(* Logix 5000 project; controller SD_Card_Example vendor 1 type 14 code 193 rev 33.12; software revision 33.01 *)

TASK MainTask (periodic, rate 1 ms, priority 10, watchdog 500 ms) : MainProgram

MODULES
   Local : vendor 1 type 14 code 193 (5069 0, rev 33.12)
END_MODULES

TYPE SD_Arrays :   // Contains the arrays that store the sent and received CIP data for the SD card library
STRUCT
   source : SINT[4000];
   destination : SINT[4000];
END_STRUCT
END_TYPE

ADD_ON_INSTRUCTION SD_CloseFile   (* revision 1.0 *)
// Closes an open file on the SD card
VAR_INPUT
   Execute : BOOL; {required}   // Execution of the function block begins on a rising edge of this input
   FileHandle : DINT; {required}   // Handle of file to close
END_VAR
VAR_OUTPUT
   Done : BOOL; {visible}   // Command has finished successfully, any returned values can be used
   Error : BOOL; {visible}   // Error occured during execution
   ErrorCode : INT; {visible}   // CIP message error code
   ErrorCodeExtended : DINT; {visible}   // CIP message error code extended
END_VAR
VAR_IN_OUT
   Message_54 : MESSAGE; {required}   // Message to send to SD card reader, MUST HAVE SERVICE CODE 54!!!
   Arrays : SD_Arrays; {required}
END_VAR

ROUTINE Logic   (* ladder *)
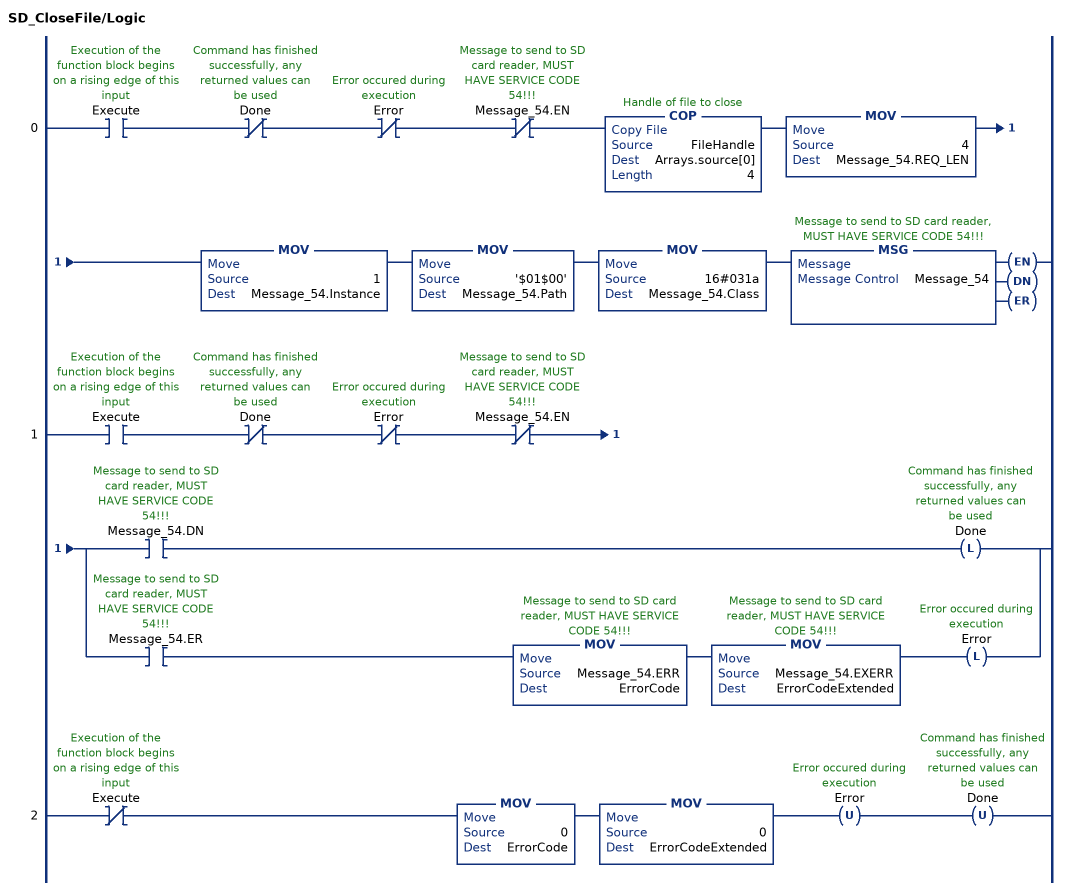
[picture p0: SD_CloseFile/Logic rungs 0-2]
   0: XIC(Execute)XIO(Done)XIO(Error)XIO(Message_54.EN)COP(FileHandle,Arrays.source[0],4)MOV(4,Message_54.REQ_LEN)MOV(1,Message_54.Instance)MOV('$01$00',Message_54.Path)MOV(16#031a,Message_54.Class)MSG(Message_54);
   1: XIC(Execute)XIO(Done)XIO(Error)XIO(Message_54.EN)[XIC(Message_54.DN) OTL(Done) ,XIC(Message_54.ER) MOV(Message_54.ERR,ErrorCode) MOV(Message_54.EXERR,ErrorCodeExtended) OTL(Error) ];
   2: XIO(Execute)MOV(0,ErrorCode)MOV(0,ErrorCodeExtended)OTU(Error)OTU(Done);
END_ROUTINE
END_ADD_ON_INSTRUCTION

ADD_ON_INSTRUCTION SD_CreateFile   (* revision 1.0 *)
// Creates and opens file on the SD card (will return an error if the file already exist on the card)
VAR_INPUT
   Execute : BOOL; {required}   // Execution of the function block begins on a rising edge of this input
END_VAR
VAR_IN_OUT
   FileName : STRING; {required}   // Name of the file
END_VAR
VAR_OUTPUT
   Done : BOOL; {visible}   // Command has finished successfully, any returned values can be used
   Error : BOOL; {visible}   // Error occured during execution
   ErrorCode : INT; {visible}   // CIP message error code
   ErrorCodeExtended : DINT; {visible}   // CIP message error code extended
   FileHandle : DINT; {visible}   // Returned file handle
END_VAR
VAR_IN_OUT
   Message_52 : MESSAGE; {required}   // Message to send to SD card reader, MUST HAVE SERVICE CODE 52!!!
   Arrays : SD_Arrays; {required}
END_VAR
VAR
   OpenCreateParameters : SINT[24] := ([3] := -64, [12] := 1, [16] := -128); {access None}
   MessageReady : BOOL; {access None}
   RequestCleared : BOOL; {access None}
   LoopCount : DINT; {access None}
END_VAR

ROUTINE Logic   (* ladder *)
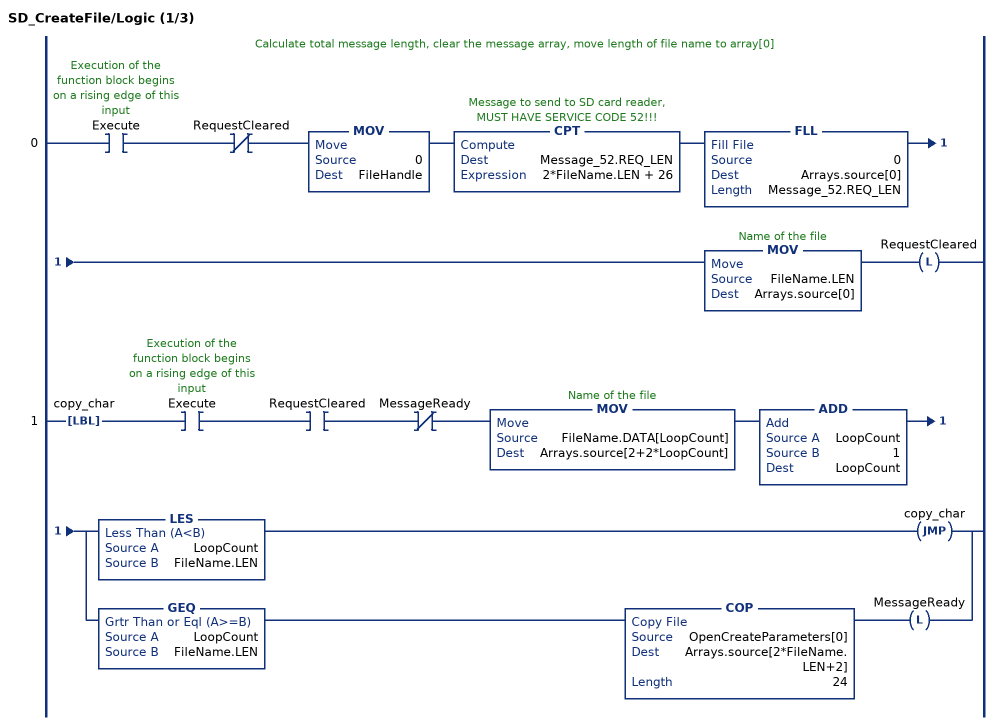
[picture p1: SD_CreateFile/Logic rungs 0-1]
   // Calculate total message length, clear the message array, move length of file name to array[0]
   0: XIC(Execute)XIO(RequestCleared)MOV(0,FileHandle)CPT(Message_52.REQ_LEN,2*FileName.LEN + 26)FLL(0,Arrays.source[0],Message_52.REQ_LEN)MOV(FileName.LEN,Arrays.source[0])OTL(RequestCleared);
   1: LBL(copy_char)XIC(Execute)XIC(RequestCleared)XIO(MessageReady)MOV(FileName.DATA[LoopCount],Arrays.source[2+2*LoopCount])ADD(LoopCount,1,LoopCount)[LES(LoopCount,FileName.LEN) JMP(copy_char) ,GEQ(LoopCount,FileName.LEN) COP(OpenCreateParameters[0],Arrays.source[2*FileName.LEN+2],24) OTL(MessageReady) ];
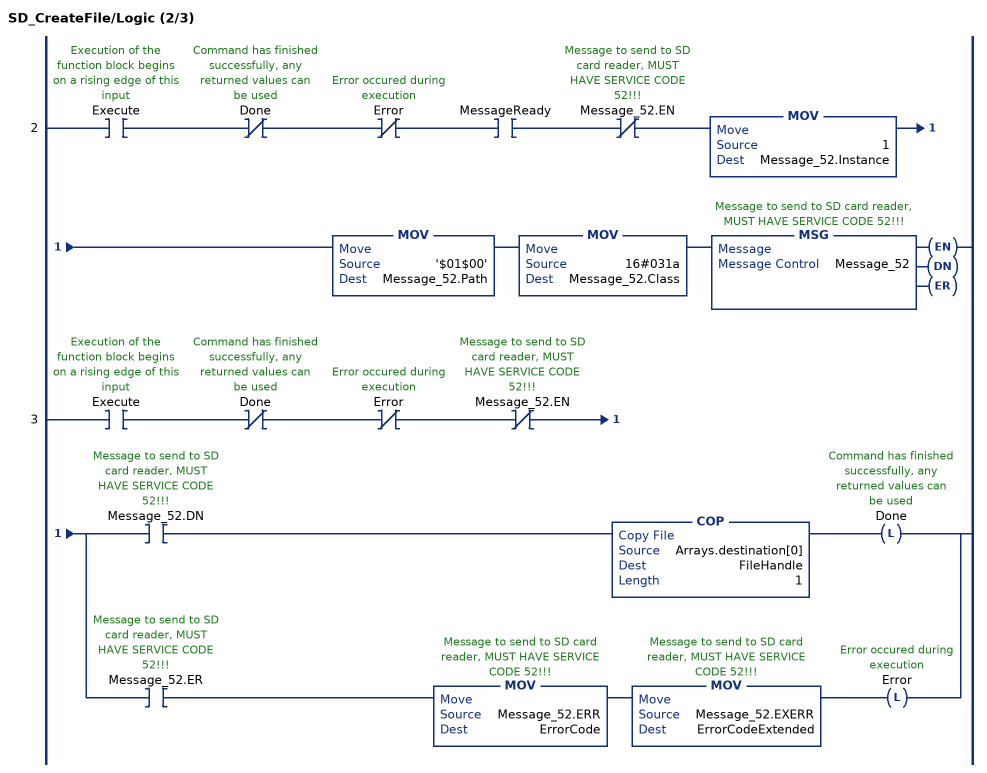
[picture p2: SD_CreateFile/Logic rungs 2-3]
   2: XIC(Execute)XIO(Done)XIO(Error)XIC(MessageReady)XIO(Message_52.EN)MOV(1,Message_52.Instance)MOV('$01$00',Message_52.Path)MOV(16#031a,Message_52.Class)MSG(Message_52);
   3: XIC(Execute)XIO(Done)XIO(Error)XIO(Message_52.EN)[XIC(Message_52.DN) COP(Arrays.destination[0],FileHandle,1) OTL(Done) ,XIC(Message_52.ER) MOV(Message_52.ERR,ErrorCode) MOV(Message_52.EXERR,ErrorCodeExtended) OTL(Error) ];
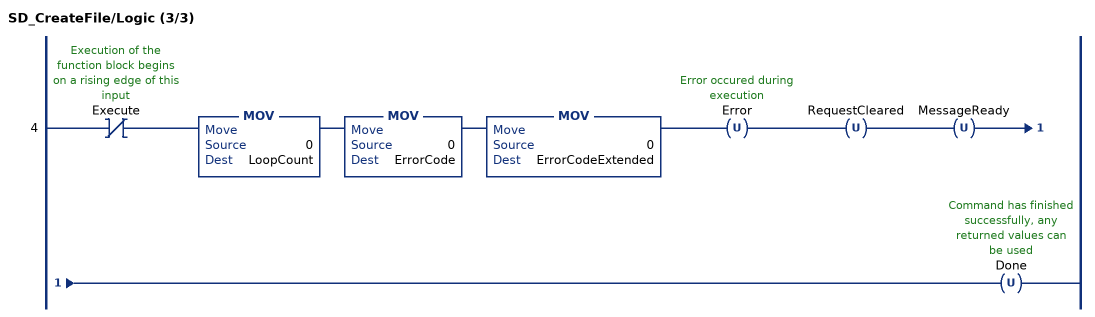
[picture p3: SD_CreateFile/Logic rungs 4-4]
   4: XIO(Execute)MOV(0,LoopCount)MOV(0,ErrorCode)MOV(0,ErrorCodeExtended)OTU(Error)OTU(RequestCleared)OTU(MessageReady)OTU(Done);
END_ROUTINE
END_ADD_ON_INSTRUCTION

ADD_ON_INSTRUCTION SD_DeleteFile   (* revision 1.0 *)
// Deletes a file on the SD card
VAR_INPUT
   Execute : BOOL; {required}   // Execution of the function block begins on a rising edge of this input
END_VAR
VAR_IN_OUT
   FileName : STRING; {required}   // Name of the file
END_VAR
VAR_OUTPUT
   Done : BOOL; {visible}   // Command has finished successfully, any returned values can be used
   Error : BOOL; {visible}   // Error occured during execution
   ErrorCode : INT; {visible}   // CIP message error code
   ErrorCodeExtended : DINT; {visible}   // CIP message error code extended
END_VAR
VAR_IN_OUT
   Message_55 : MESSAGE; {required}   // Message to send to SD card reader, MUST HAVE SERVICE CODE 55!!!
   Arrays : SD_Arrays; {required}
END_VAR
VAR
   MessageReady : BOOL; {access None}
   RequestCleared : BOOL; {access None}
   LoopCount : DINT; {access None}
END_VAR

ROUTINE Logic   (* ladder *)
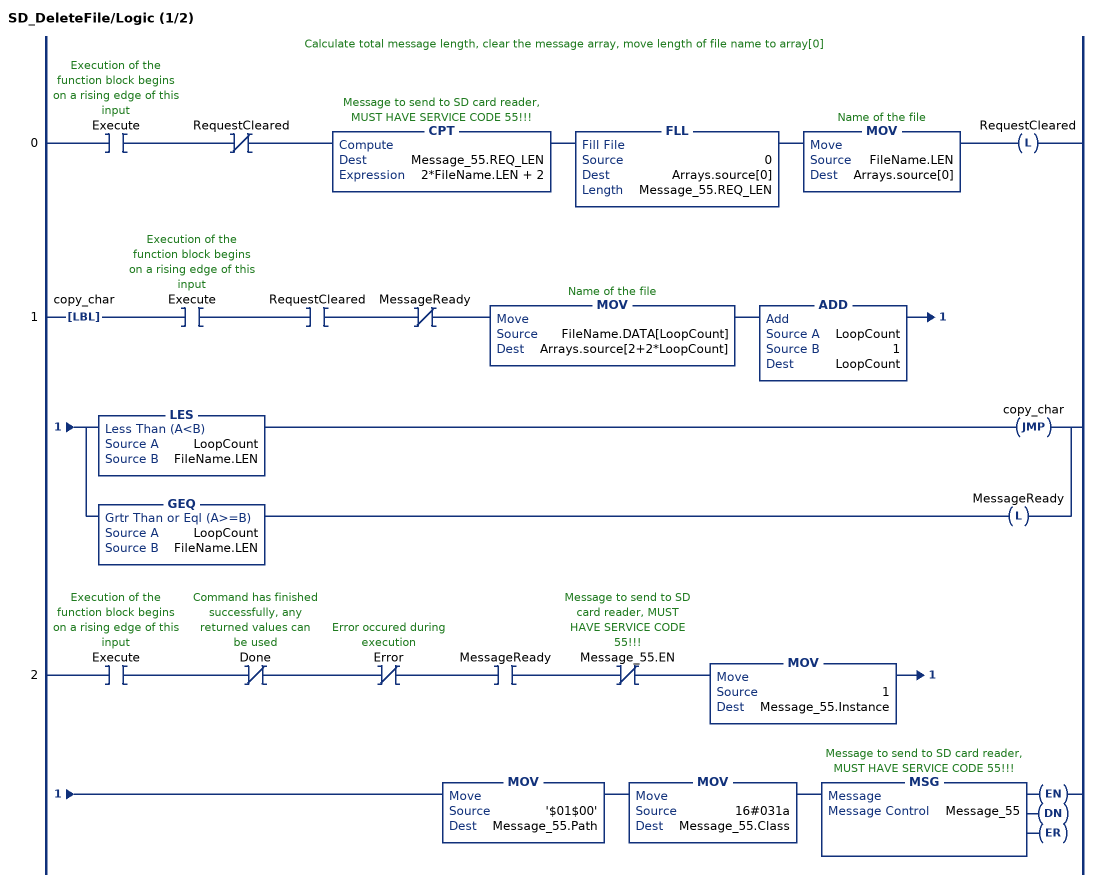
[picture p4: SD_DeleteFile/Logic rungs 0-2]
   // Calculate total message length, clear the message array, move length of file name to array[0]
   0: XIC(Execute)XIO(RequestCleared)CPT(Message_55.REQ_LEN,2*FileName.LEN + 2)FLL(0,Arrays.source[0],Message_55.REQ_LEN)MOV(FileName.LEN,Arrays.source[0])OTL(RequestCleared);
   1: LBL(copy_char)XIC(Execute)XIC(RequestCleared)XIO(MessageReady)MOV(FileName.DATA[LoopCount],Arrays.source[2+2*LoopCount])ADD(LoopCount,1,LoopCount)[LES(LoopCount,FileName.LEN) JMP(copy_char) ,GEQ(LoopCount,FileName.LEN) OTL(MessageReady) ];
   2: XIC(Execute)XIO(Done)XIO(Error)XIC(MessageReady)XIO(Message_55.EN)MOV(1,Message_55.Instance)MOV('$01$00',Message_55.Path)MOV(16#031a,Message_55.Class)MSG(Message_55);
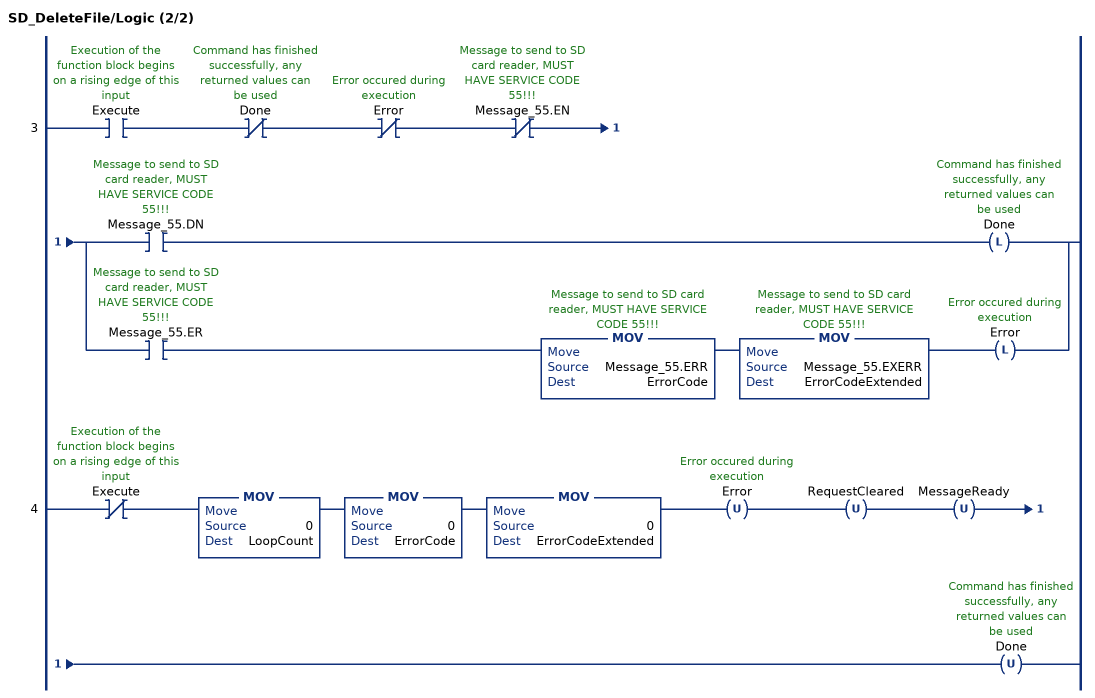
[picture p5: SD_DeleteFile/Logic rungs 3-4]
   3: XIC(Execute)XIO(Done)XIO(Error)XIO(Message_55.EN)[XIC(Message_55.DN) OTL(Done) ,XIC(Message_55.ER) MOV(Message_55.ERR,ErrorCode) MOV(Message_55.EXERR,ErrorCodeExtended) OTL(Error) ];
   4: XIO(Execute)MOV(0,LoopCount)MOV(0,ErrorCode)MOV(0,ErrorCodeExtended)OTU(Error)OTU(RequestCleared)OTU(MessageReady)OTU(Done);
END_ROUTINE
END_ADD_ON_INSTRUCTION

ADD_ON_INSTRUCTION SD_DetectCard   (* revision 1.0 *)
// Detects whether the SD card is present
VAR_INPUT
   Execute : BOOL; {required}   // Execution of the function block begins on a rising edge of this input
END_VAR
VAR_OUTPUT
   Done : BOOL; {visible}   // Command has finished successfully, any returned values can be used
   Error : BOOL; {visible}   // Error occured during execution
   ErrorCode : INT; {visible}   // CIP message error code
   ErrorCodeExtended : DINT; {visible}   // CIP message error code extended
   CardPresent : BOOL; {visible}   // SD card detected
END_VAR
VAR_IN_OUT
   Message_03 : MESSAGE; {required}   // Message to send to SD card reader, MUST HAVE SERVICE CODE 03!!!
   Arrays : SD_Arrays; {required}
END_VAR
VAR
   Get_Status : SINT[4] := ([0] := 1, [2] := 3); {access None}
END_VAR

ROUTINE Logic   (* ladder *)
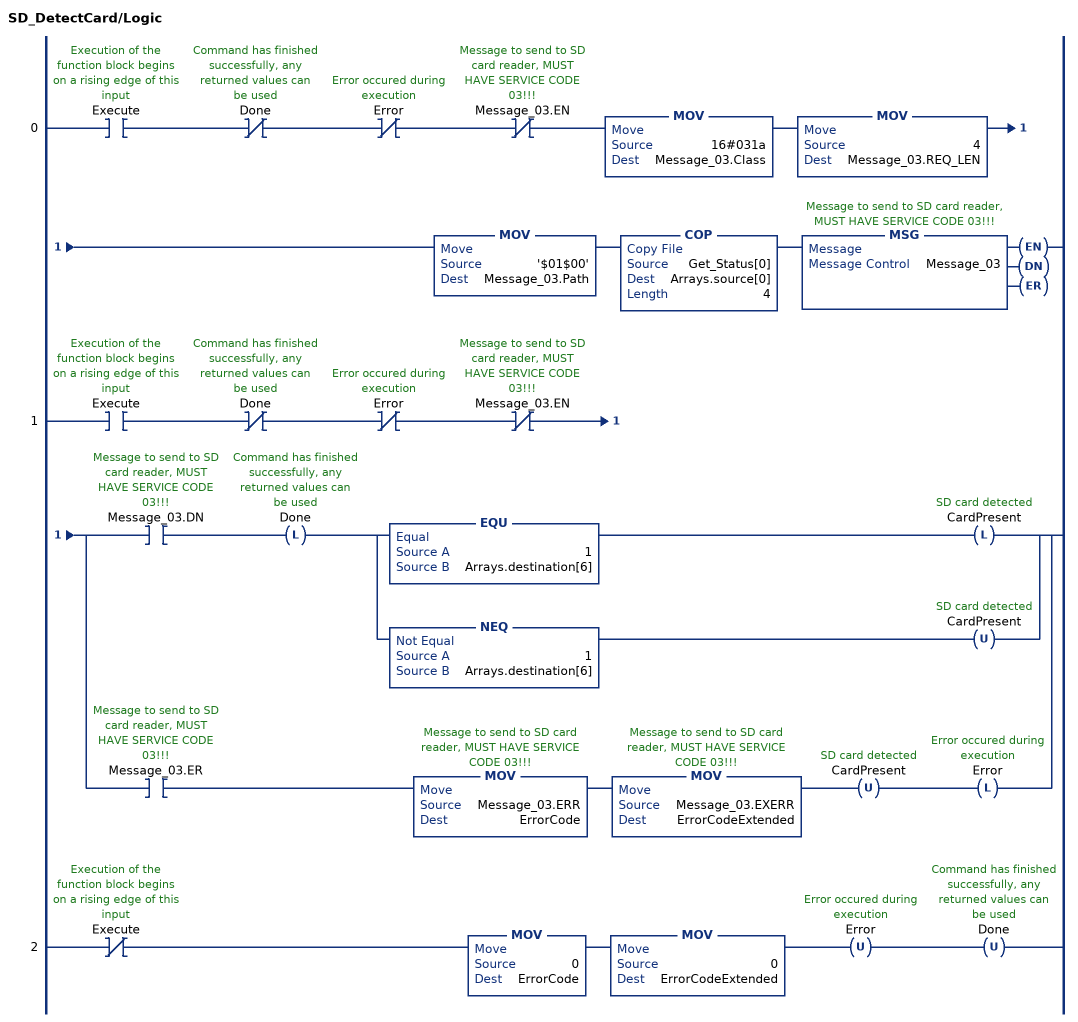
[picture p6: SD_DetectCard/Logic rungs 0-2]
   0: XIC(Execute)XIO(Done)XIO(Error)XIO(Message_03.EN)MOV(16#031a,Message_03.Class)MOV(4,Message_03.REQ_LEN)MOV('$01$00',Message_03.Path)COP(Get_Status[0],Arrays.source[0],4)MSG(Message_03);
   1: XIC(Execute)XIO(Done)XIO(Error)XIO(Message_03.EN)[XIC(Message_03.DN) OTL(Done) [EQU(1,Arrays.destination[6]) OTL(CardPresent) ,NEQ(1,Arrays.destination[6]) OTU(CardPresent) ] ,XIC(Message_03.ER) MOV(Message_03.ERR,ErrorCode) MOV(Message_03.EXERR,ErrorCodeExtended) OTU(CardPresent) OTL(Error) ];
   2: XIO(Execute)MOV(0,ErrorCode)MOV(0,ErrorCodeExtended)OTU(Error)OTU(Done);
END_ROUTINE
END_ADD_ON_INSTRUCTION

ADD_ON_INSTRUCTION SD_Logging   (* revision 1.0 *)
// Create a text file for data logging. Buffer string writes to the log file and dump them to the file when the buffer is greater than a threshold. NOTE: when logging is the current contents of the buffer won't be written.
VAR_INPUT
   Execute : BOOL; {required}   // Create the logging file and start recording data
END_VAR
VAR_IN_OUT
   FileName : STRING; {required}   // Name of the log file to create
END_VAR
VAR_INPUT
   BufferSize : DINT := 1000; {required}   // Number of bytes to buffer before dumping to file (must be < 65535)
END_VAR
VAR_IN_OUT
   NewString : STRING; {required}   // New data to add to the log file. If you don't wish to add new data this cycle give an empty string
END_VAR
VAR_INPUT
   StopLogging : BOOL; {required}   // Stop the logging process and close the file.
END_VAR
VAR_OUTPUT
   LoggingReady : BOOL; {visible}   // Log file has been created and logging has begun
   LoggingFinished : BOOL; {visible}   // File has been closed and the SD card can be safely removed
   Error : BOOL; {visible}   // Error occured during execution
   ErrorCode : INT; {visible}   // CIP message error code
   ErrorCodeExtended : DINT; {visible}   // CIP message error code extended
END_VAR
VAR_IN_OUT
   WriteFileArray : SINT[500000]; {required}   // Array for writing to the file
   Message_52 : MESSAGE; {required}   // Message to send to SD card reader, MUST HAVE SERVICE CODE 52!!!
   Message_50 : MESSAGE; {required}   // Message to send to SD card reader, MUST HAVE SERVICE CODE 50!!!
   Message_54 : MESSAGE; {required}   // Message to send to SD card reader, MUST HAVE SERVICE CODE 54!!!
   Arrays : SD_Arrays; {required}
END_VAR
VAR
   CloseFile : SD_CloseFile; {access None}
   WriteFile : SD_WriteFile; {access None}
   CreateFile : SD_CreateFile; {access None}
   CloseFileExecute : BOOL; {access None}
   CurrentlyWriting : BOOL; {access None}
   BufferDataSize : DINT; {access None}
   DataBeingWrittenSize : DINT; {access None}
   BufferData : SINT[65535]; {access None}
END_VAR

ROUTINE Logic   (* structured text *)
// Create a text file for data logging. Buffer string writes to the log file and dump them to the file when the buffer is greater than a threshold.
   //reset logging
   if(not(Execute))then
   	CurrentlyWriting := 0;
   	DataBeingWrittenSize := 0;
   	BufferDataSize := 0;
   	StopLogging := 0;
   	LoggingReady := 0;
   	LoggingFinished := 0;
   	Error := 0;
   	ErrorCode := 0;
   	ErrorCodeExtended := 0;
   end_if;
   
   //Create the log file
   SD_CreateFile(CreateFile,Execute,FileName,Message_52,Arrays);
   LoggingReady := CreateFile.Done;
   
   //Record the data
   if(CreateFile.Done)then
   	//write new data to log buffer
   	if(not(StopLogging))then
   		COP(NewString.DATA[0],BufferData[BufferDataSize],NewString.LEN);
   		BufferDataSize := BufferDataSize + NewString.LEN;
   		//if enough data recorded, dump to file
   		if(BufferDataSize >= BufferSize)then
   			CurrentlyWriting := 1;
   		end_if;
   	end_if;
   
   	//copy log buffer to writing buffer. Then reset log buffer
   	if(CurrentlyWriting and DataBeingWrittenSize = 0)then
   		COP(BufferData[0],WriteFileArray[0],BufferDataSize);
   		DataBeingWrittenSize := BufferDataSize;
   		BufferDataSize := 0;
   	end_if;
   end_if;
   
   //write the writing buffer to the file
   SD_WriteFile(WriteFile,CurrentlyWriting,CreateFile.FileHandle,DataBeingWrittenSize,WriteFileArray,Message_50,Arrays);
   if(WriteFile.Done)then
   	CurrentlyWriting := 0;
   	DataBeingWrittenSize := 0;
   end_if;
   
   //close the file
   CloseFileExecute := StopLogging and not(CurrentlyWriting);
   SD_CloseFile(CloseFile,CloseFileExecute,CreateFile.FileHandle,Message_54,Arrays);
   LoggingFinished := CloseFile.Done;
   
   //Error handling
   if(CreateFile.Error)then
   	Error := CreateFile.Error;
   	ErrorCode := CreateFile.ErrorCode;
   	ErrorCodeExtended := CreateFile.ErrorCodeExtended;
   end_if;
   if(WriteFile.Error)then
   	Error := WriteFile.Error;
   	ErrorCode := WriteFile.ErrorCode;
   	ErrorCodeExtended := WriteFile.ErrorCodeExtended;
   end_if;
   if(CloseFile.Error)then
   	Error := CloseFile.Error;
   	ErrorCode := CloseFile.ErrorCode;
   	ErrorCodeExtended := CloseFile.ErrorCodeExtended;
   end_if;
   if(Error)then //reset buffer if error occurs to prevent buffer overflow
   	CurrentlyWriting := 0;
   	DataBeingWrittenSize := 0;
   	BufferDataSize := 0;
   end_if;
END_ROUTINE
END_ADD_ON_INSTRUCTION

ADD_ON_INSTRUCTION SD_OpenFile   (* revision 1.0 *)
// Opens a file on the SD card (will return error if file doesn't exist on the SD card)
VAR_INPUT
   Execute : BOOL; {required}   // Execution of the function block begins on a rising edge of this input
END_VAR
VAR_IN_OUT
   FileName : STRING; {required}   // Name of the file
END_VAR
VAR_OUTPUT
   Done : BOOL; {visible}   // Command has finished successfully, any returned values can be used
   Error : BOOL; {visible}   // Error occured during execution
   ErrorCode : INT; {visible}   // CIP message error code
   ErrorCodeExtended : DINT; {visible}   // CIP message error code extended
   FileHandle : DINT; {visible}   // Returned file handle
END_VAR
VAR_IN_OUT
   Message_52 : MESSAGE; {required}   // Message to send to SD card reader, MUST HAVE SERVICE CODE 52!!!
   Arrays : SD_Arrays; {required}
END_VAR
VAR
   OpenCreateParameters : SINT[24] := ([3] := -64, [12] := 3, [16] := -128); {access None}
   MessageReady : BOOL; {access None}
   RequestCleared : BOOL; {access None}
   LoopCount : DINT; {access None}
END_VAR

ROUTINE Logic   (* ladder *)
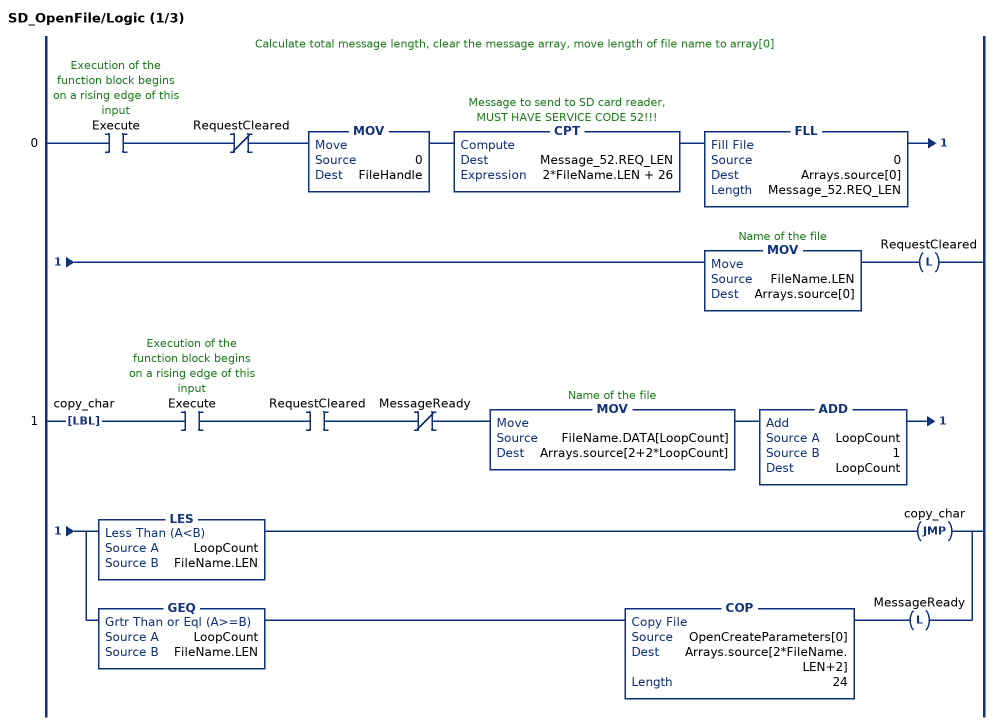
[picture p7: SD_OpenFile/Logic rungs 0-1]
   // Calculate total message length, clear the message array, move length of file name to array[0]
   0: XIC(Execute)XIO(RequestCleared)MOV(0,FileHandle)CPT(Message_52.REQ_LEN,2*FileName.LEN + 26)FLL(0,Arrays.source[0],Message_52.REQ_LEN)MOV(FileName.LEN,Arrays.source[0])OTL(RequestCleared);
   1: LBL(copy_char)XIC(Execute)XIC(RequestCleared)XIO(MessageReady)MOV(FileName.DATA[LoopCount],Arrays.source[2+2*LoopCount])ADD(LoopCount,1,LoopCount)[LES(LoopCount,FileName.LEN) JMP(copy_char) ,GEQ(LoopCount,FileName.LEN) COP(OpenCreateParameters[0],Arrays.source[2*FileName.LEN+2],24) OTL(MessageReady) ];
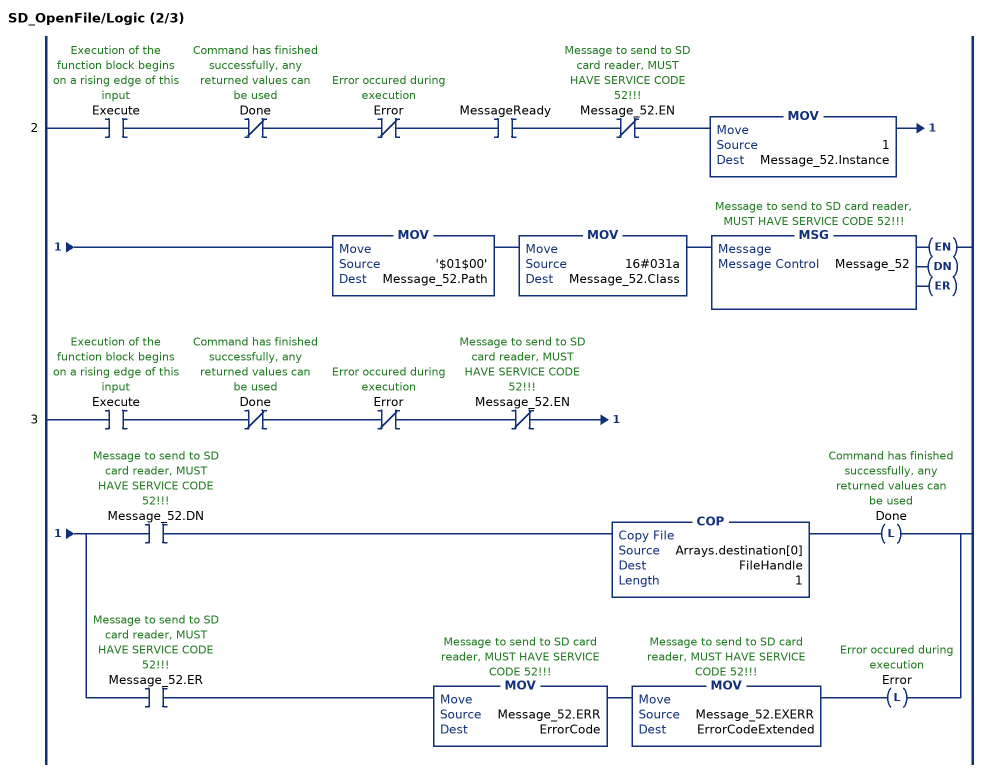
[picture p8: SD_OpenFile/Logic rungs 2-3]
   2: XIC(Execute)XIO(Done)XIO(Error)XIC(MessageReady)XIO(Message_52.EN)MOV(1,Message_52.Instance)MOV('$01$00',Message_52.Path)MOV(16#031a,Message_52.Class)MSG(Message_52);
   3: XIC(Execute)XIO(Done)XIO(Error)XIO(Message_52.EN)[XIC(Message_52.DN) COP(Arrays.destination[0],FileHandle,1) OTL(Done) ,XIC(Message_52.ER) MOV(Message_52.ERR,ErrorCode) MOV(Message_52.EXERR,ErrorCodeExtended) OTL(Error) ];
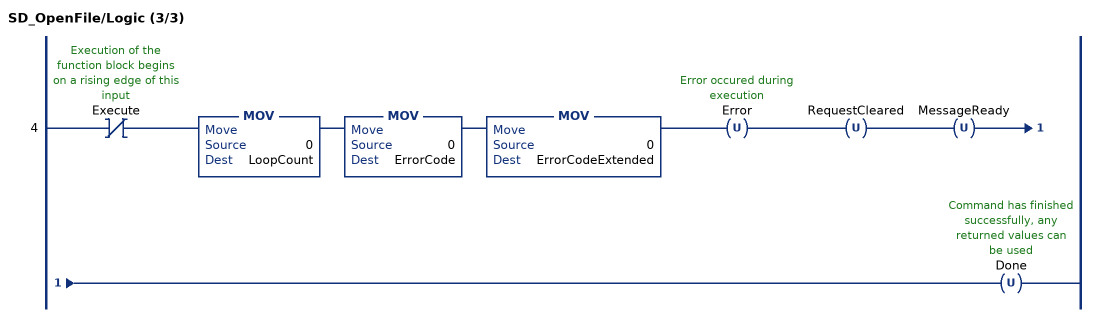
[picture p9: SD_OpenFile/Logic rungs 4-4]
   4: XIO(Execute)MOV(0,LoopCount)MOV(0,ErrorCode)MOV(0,ErrorCodeExtended)OTU(Error)OTU(RequestCleared)OTU(MessageReady)OTU(Done);
END_ROUTINE
END_ADD_ON_INSTRUCTION

ADD_ON_INSTRUCTION SD_ReadFile   (* revision 1.0 *)
// Reads data from a file on the SD card
VAR_INPUT
   Execute : BOOL; {required}   // Execution of the function block begins on a rising edge of this input
   FileHandle : DINT; {required}   // Returned file handle
END_VAR
VAR_OUTPUT
   Done : BOOL; {visible}   // Command has finished successfully, any returned values can be used
   Error : BOOL; {visible}   // Error occured during execution
   ErrorCode : INT; {visible}   // CIP message error code
   ErrorCodeExtended : DINT; {visible}   // CIP message error code extended
   NumBytes : DINT; {visible}   // Number of bytes read
END_VAR
VAR_IN_OUT
   Data : SINT[500000]; {required}   // Data read as a raw binary
   Message_4F : MESSAGE; {required}   // Message to send to SD card reader, MUST HAVE SERVICE CODE 4F!!!
   Arrays : SD_Arrays; {required}
END_VAR
VAR
   TransferSize : INT := 3994; {access None}
   LastNumBytesRead : INT; {access None}
   DoNewTransfer : BOOL; {access None}
   SetupDone : BOOL; {access None}
END_VAR

ROUTINE Logic   (* ladder *)
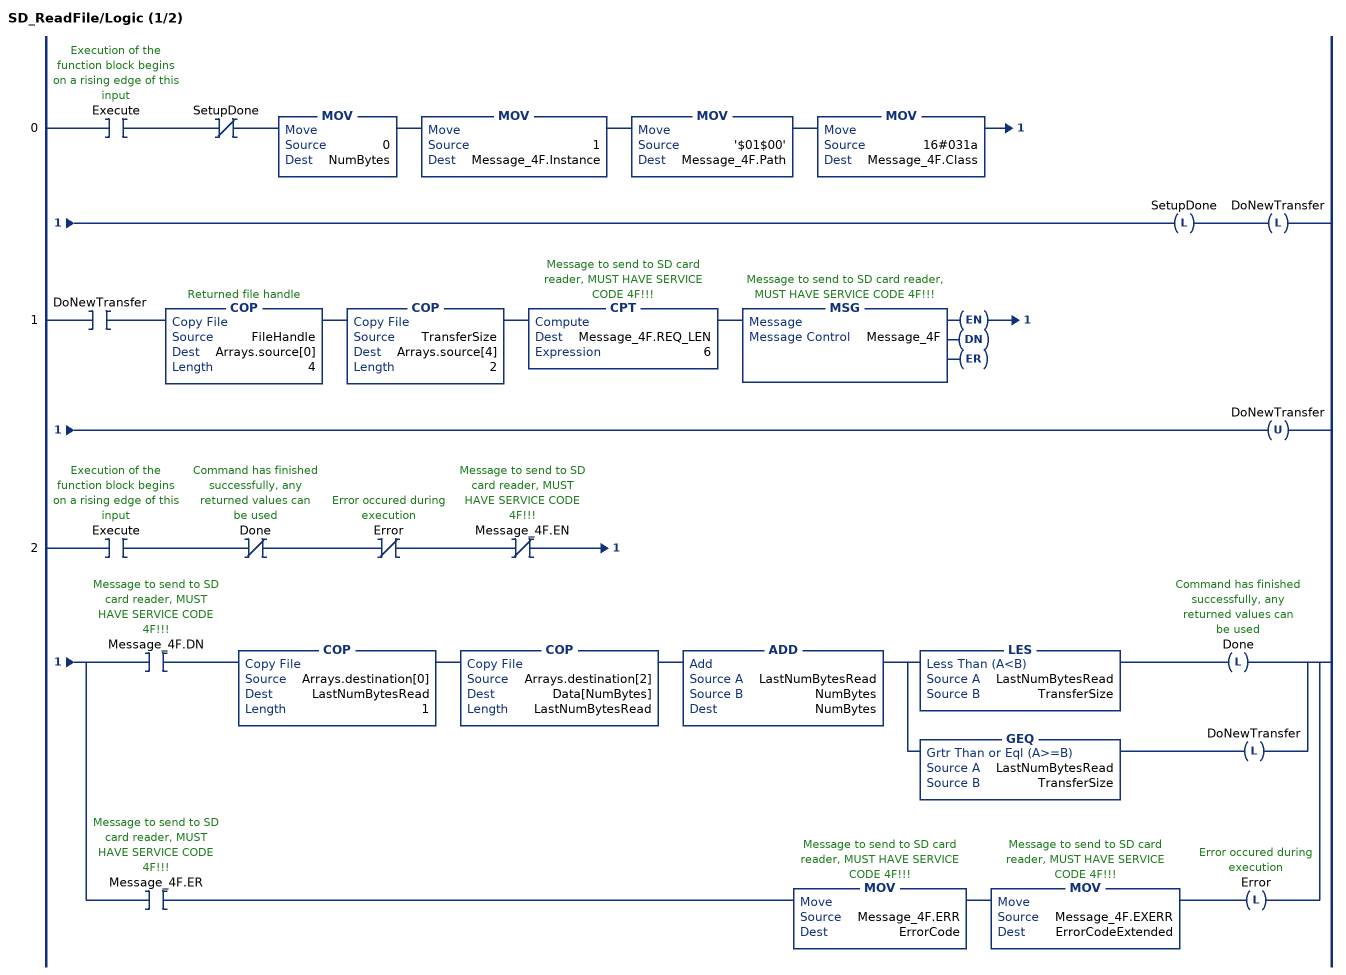
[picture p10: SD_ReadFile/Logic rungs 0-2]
   0: XIC(Execute)XIO(SetupDone)MOV(0,NumBytes)MOV(1,Message_4F.Instance)MOV('$01$00',Message_4F.Path)MOV(16#031a,Message_4F.Class)OTL(SetupDone)OTL(DoNewTransfer);
   1: XIC(DoNewTransfer)COP(FileHandle,Arrays.source[0],4)COP(TransferSize,Arrays.source[4],2)CPT(Message_4F.REQ_LEN,6)MSG(Message_4F)OTU(DoNewTransfer);
   2: XIC(Execute)XIO(Done)XIO(Error)XIO(Message_4F.EN)[XIC(Message_4F.DN) COP(Arrays.destination[0],LastNumBytesRead,1) COP(Arrays.destination[2],Data[NumBytes],LastNumBytesRead) ADD(LastNumBytesRead,NumBytes,NumBytes) [LES(LastNumBytesRead,TransferSize) OTL(Done) ,GEQ(LastNumBytesRead,TransferSize) OTL(DoNewTransfer) ] ,XIC(Message_4F.ER) MOV(Message_4F.ERR,ErrorCode) MOV(Message_4F.EXERR,ErrorCodeExtended) OTL(Error) ];
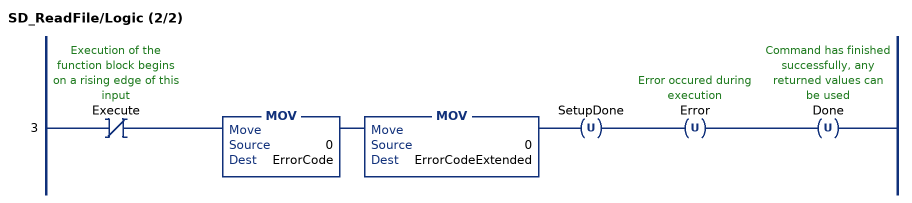
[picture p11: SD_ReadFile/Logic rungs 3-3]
   3: XIO(Execute)MOV(0,ErrorCode)MOV(0,ErrorCodeExtended)OTU(SetupDone)OTU(Error)OTU(Done);
END_ROUTINE
END_ADD_ON_INSTRUCTION

ADD_ON_INSTRUCTION SD_WriteFile   (* revision 1.0 *)
// Writes data to a file on the SD card
VAR_INPUT
   Execute : BOOL; {required}   // Execution of the function block begins on a rising edge of this input
   FileHandle : DINT; {required}   // Returned file handle
   NumBytes : DINT; {required}   // Number of bytes to write
END_VAR
VAR_IN_OUT
   Data : SINT[500000]; {required}   // Data to write as a raw binary
END_VAR
VAR_OUTPUT
   Done : BOOL; {visible}   // Command has finished successfully, any returned values can be used
   Error : BOOL; {visible}   // Error occured during execution
   ErrorCode : INT; {visible}   // CIP message error code
   ErrorCodeExtended : DINT; {visible}   // CIP message error code extended
END_VAR
VAR_IN_OUT
   Message_50 : MESSAGE; {required}   // Message to send to SD card reader, MUST HAVE SERVICE CODE 50!!!
   Arrays : SD_Arrays; {required}
END_VAR
VAR
   TransferSize : INT := 3986; {access None}
   NumBytesToSend : INT; {access None}
   NumBytesSent : DINT; {access None}
   DoNewTransfer : BOOL; {access None}
   SetupDone : BOOL; {access None}
   NumBytesLeft : DINT; {access None}
END_VAR

ROUTINE Logic   (* ladder *)
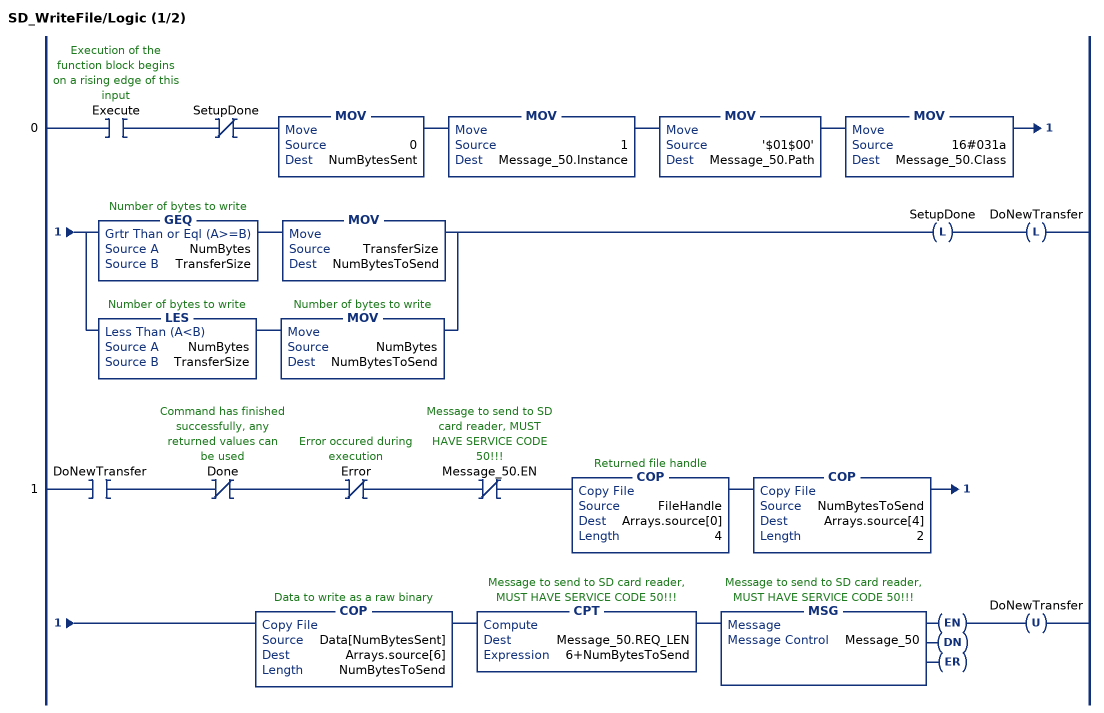
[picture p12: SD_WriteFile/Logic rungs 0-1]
   0: XIC(Execute)XIO(SetupDone)MOV(0,NumBytesSent)MOV(1,Message_50.Instance)MOV('$01$00',Message_50.Path)MOV(16#031a,Message_50.Class)[GEQ(NumBytes,TransferSize) MOV(TransferSize,NumBytesToSend) ,LES(NumBytes,TransferSize) MOV(NumBytes,NumBytesToSend) ]OTL(SetupDone)OTL(DoNewTransfer);
   1: XIC(DoNewTransfer)XIO(Done)XIO(Error)XIO(Message_50.EN)COP(FileHandle,Arrays.source[0],4)COP(NumBytesToSend,Arrays.source[4],2)COP(Data[NumBytesSent],Arrays.source[6],NumBytesToSend)CPT(Message_50.REQ_LEN,6+NumBytesToSend)MSG(Message_50)OTU(DoNewTransfer);
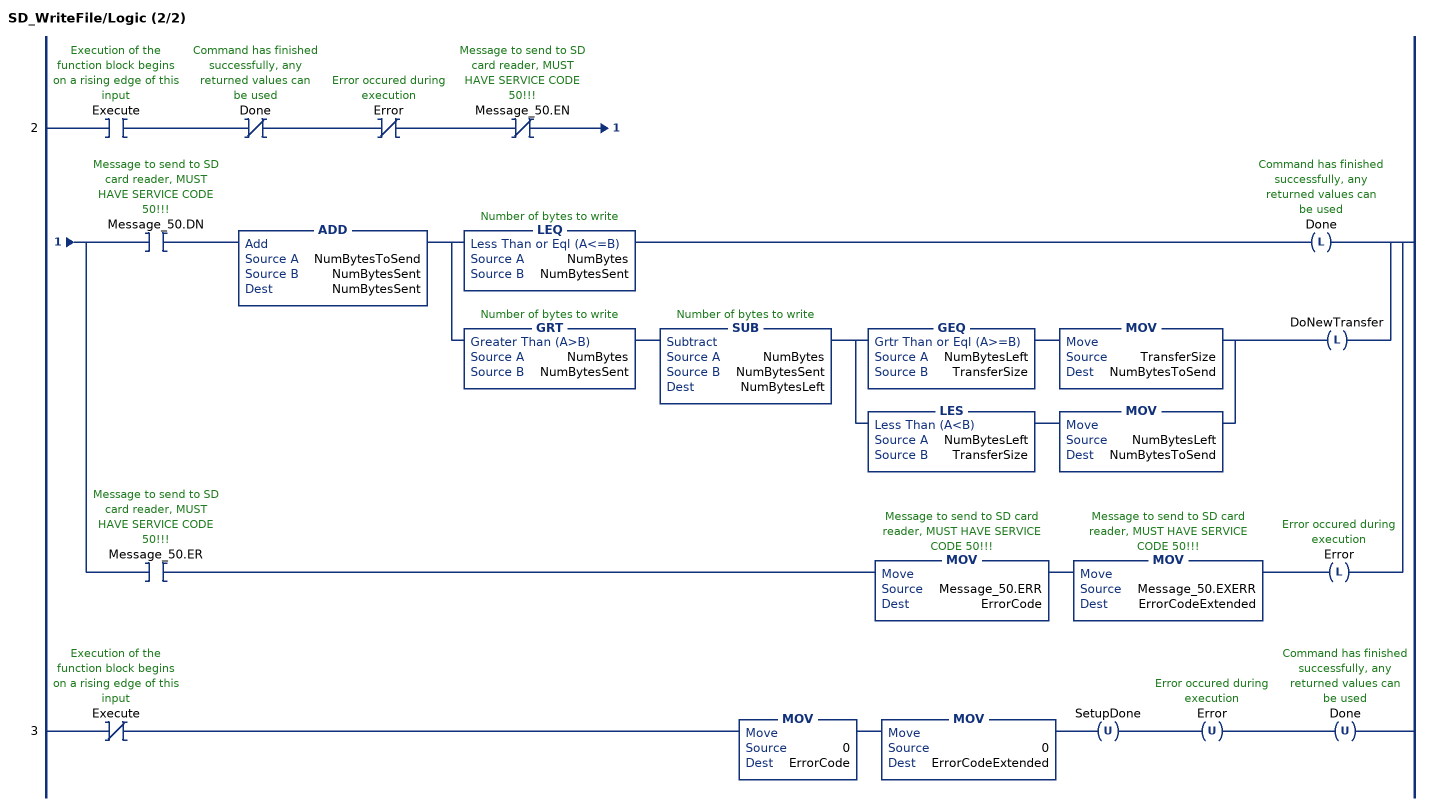
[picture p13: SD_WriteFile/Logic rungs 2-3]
   2: XIC(Execute)XIO(Done)XIO(Error)XIO(Message_50.EN)[XIC(Message_50.DN) ADD(NumBytesToSend,NumBytesSent,NumBytesSent) [LEQ(NumBytes,NumBytesSent) OTL(Done) ,GRT(NumBytes,NumBytesSent) SUB(NumBytes,NumBytesSent,NumBytesLeft) [GEQ(NumBytesLeft,TransferSize) MOV(TransferSize,NumBytesToSend) ,LES(NumBytesLeft,TransferSize) MOV(NumBytesLeft,NumBytesToSend) ] OTL(DoNewTransfer) ] ,XIC(Message_50.ER) MOV(Message_50.ERR,ErrorCode) MOV(Message_50.EXERR,ErrorCodeExtended) OTL(Error) ];
   3: XIO(Execute)MOV(0,ErrorCode)MOV(0,ErrorCodeExtended)OTU(SetupDone)OTU(Error)OTU(Done);
END_ROUTINE
END_ADD_ON_INSTRUCTION

PROGRAM MainProgram   (* main routine MainRoutine *)
VAR
   Arrays : SD_Arrays;
   CloseFile : SD_CloseFile;
   CloseFileExecute : BOOL;
   CreateFile : SD_CreateFile;
   CreateFileExecute : BOOL;
   DeleteFile : SD_DeleteFile;
   DeleteFileExecute : BOOL;
   DetectCard : SD_DetectCard;
   DetectCardExecute : BOOL;
   FileData : SINT[500000];
   FileHandle : DINT;
   Filename : STRING := 'test_read.txt';
   Message03 : MESSAGE;
        MessageParameters(ServiceCode := 16#0003, LocalElement := Arrays.source, DestinationTag := Arrays.destination, ...)
   Message4F : MESSAGE;
        MessageParameters(ServiceCode := 16#004f, LocalElement := Arrays.source, DestinationTag := Arrays.destination, ...)
   Message50 : MESSAGE;
        MessageParameters(ServiceCode := 16#0050, LocalElement := Arrays.source, DestinationTag := Arrays.destination, ...)
   Message52Create : MESSAGE;
        MessageParameters(ServiceCode := 16#0052, LocalElement := Arrays.source, DestinationTag := Arrays.destination, ...)
   Message52Open : MESSAGE;
        MessageParameters(ServiceCode := 16#0052, LocalElement := Arrays.source, DestinationTag := Arrays.destination, ...)
   Message54 : MESSAGE;
        MessageParameters(ServiceCode := 16#0054, LocalElement := Arrays.source, DestinationTag := Arrays.destination, ...)
   Message55 : MESSAGE;
        MessageParameters(ServiceCode := 16#0055, LocalElement := Arrays.source, DestinationTag := Arrays.destination, ...)
   OpenFile : SD_OpenFile;
   OpenFileExecute : BOOL;
   ReadFile : SD_ReadFile;
   ReadFileExecute : BOOL;
   WriteFile : SD_WriteFile;
   WriteFileExecute : BOOL;
   WriteFileNumBytes : DINT;
END_VAR

ROUTINE MainRoutine   (* structured text *)
   SD_DetectCard(DetectCard,DetectCardExecute,Message03,Arrays);
   
   SD_CreateFile(CreateFile,CreateFileExecute,Filename,Message52Create,Arrays);
   if(CreateFile.Done)then
   	FileHandle := CreateFile.FileHandle;
   end_if;
   
   SD_OpenFile(OpenFile,OpenFileExecute,Filename,Message52Open,Arrays);
   if(OpenFile.Done)then
   	FileHandle := OpenFile.FileHandle;
   end_if;
   
   SD_ReadFile(ReadFile,ReadFileExecute,FileHandle,FileData,Message4F,Arrays);
   
   SD_WriteFile(WriteFile,WriteFileExecute,FileHandle,WriteFileNumBytes,FileData,Message50,Arrays);
   
   SD_CloseFile(CloseFile,CloseFileExecute,FileHandle,Message54,Arrays);
   
   SD_DeleteFile(DeleteFile,DeleteFileExecute,Filename,Message55,Arrays);
END_ROUTINE
END_PROGRAM
